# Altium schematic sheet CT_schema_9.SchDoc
size 274 x 160 mm
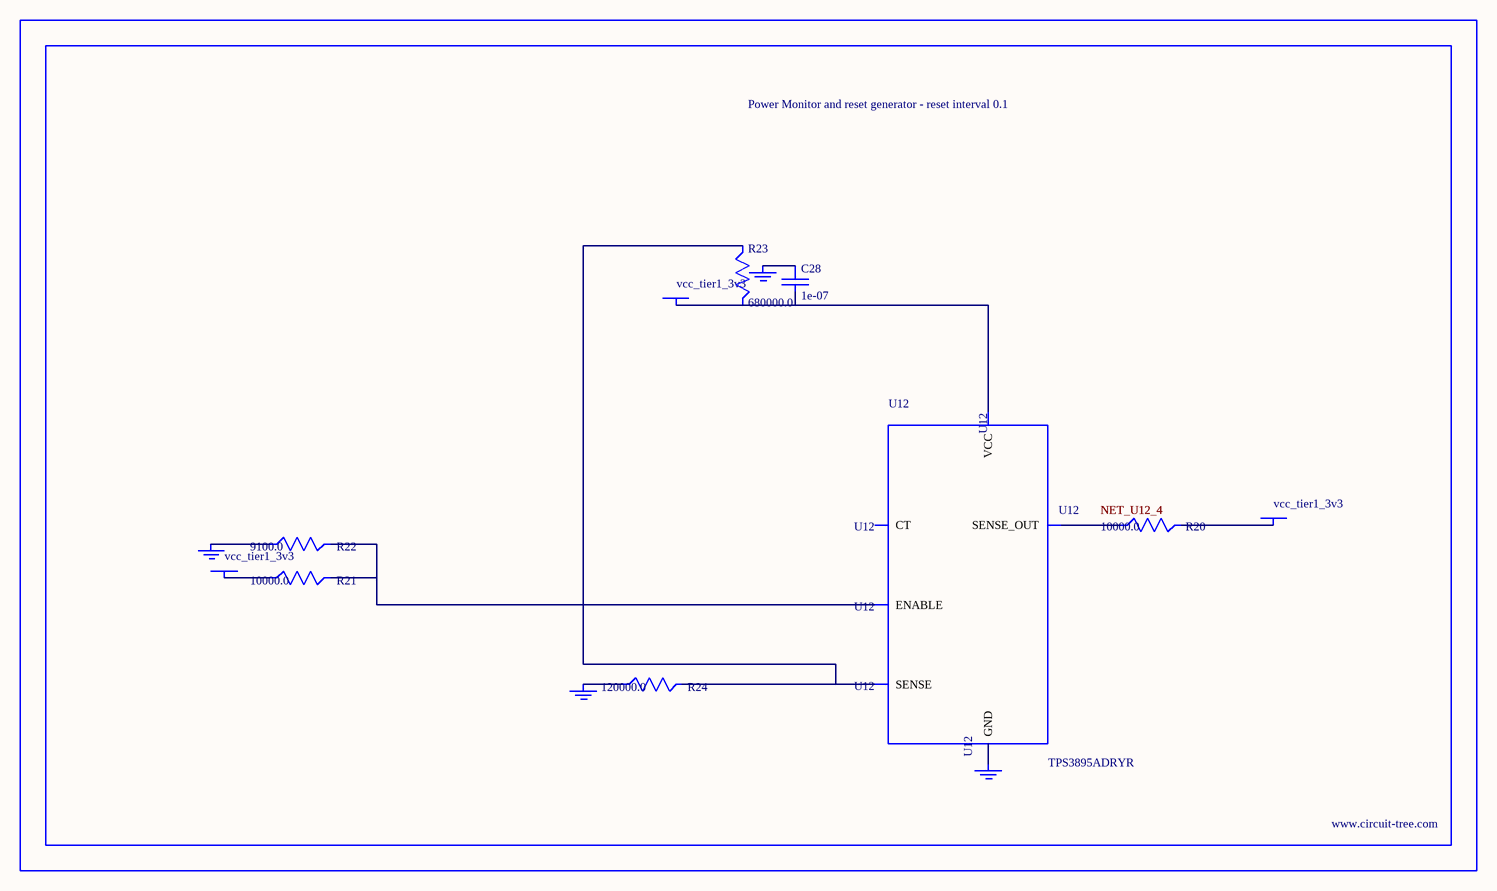
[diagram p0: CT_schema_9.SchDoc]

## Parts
BORDER8  (no value)
C28  1e-07  [C0402]
GND_INSTANCE_8_0  (no value)
GND_INSTANCE_8_1  (no value)
GND_INSTANCE_8_2  (no value)
GND_INSTANCE_8_3  (no value)
POWER_INSTANCE_8_0  vcc_tier1_3v3
POWER_INSTANCE_8_1  vcc_tier1_3v3
POWER_INSTANCE_8_2  vcc_tier1_3v3
R20  10000.0  [R0603]
R21  10000.0  [R0603]
R22  9100.0  [R0603]
R23  680000.0  [R0603]
R24  120000.0  [R0603]
U12  TPS3895ADRYR  [SON-6]

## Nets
NetC28_1: C28.1 GND_INSTANCE_8_2.0(GND)
NetC28_2: C28.2 POWER_INSTANCE_8_2.0(PWR) R23.2 U12.6(VCC)
NetGND_INSTANCE_8_0_0: GND_INSTANCE_8_0.0(GND) R22.1
NetGND_INSTANCE_8_1_0: GND_INSTANCE_8_1.0(GND) R24.1
NetGND_INSTANCE_8_3_0: GND_INSTANCE_8_3.0(GND) U12.2(GND)
NetPOWER_INSTANCE_8_0_0: POWER_INSTANCE_8_0.0(PWR) R21.1
NetPOWER_INSTANCE_8_1_0: POWER_INSTANCE_8_1.0(PWR) R20.2
NetR20_1: R20.1 U12.4(SENSE_OUT)
NetR21_2: R21.2 R22.2 U12.1(ENABLE)
NetR23_1: R23.1 R24.2 U12.3(SENSE)

Not connected (* = marked no-connect by the designer): U12 5(CT)

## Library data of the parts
BORDER8 = BORDER_PAGE8
C28 = C0402C104K3RACTU
GND_INSTANCE_8_0-GND_INSTANCE_8_3 = GND
POWER_INSTANCE_8_0-POWER_INSTANCE_8_2 = PWR
R20 R21 = RC0603JR-0710KL
R22 = RC0603JR-079K1L
R23 = RC0603JR-07680KL
R24 = RC0603JR-07120KL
